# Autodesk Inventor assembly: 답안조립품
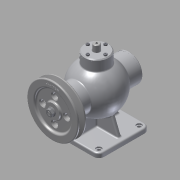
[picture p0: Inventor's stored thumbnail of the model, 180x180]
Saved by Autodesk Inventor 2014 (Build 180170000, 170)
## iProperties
Created: 2015-10
Part Number: 답안조립품
Document SubType Name: Assembly
Designer: youjin08
Author: youjin08
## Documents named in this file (19)
- C:\Users\youjin08\Desktop\451010V1010\답안조립품.iam
- C:\Users\youjin08\Desktop\451010V1010\본체.ipt
- C:\Users\youjin08\Desktop\451010V1010\앞커버.ipt
- C:\Users\youjin08\Desktop\451010V1010\뒤커버.ipt
- C:\Users\youjin08\Desktop\451010V1010\볼트 M4 x 16.ipt
- C:\Users\youjin08\Desktop\451010V1010\상부커버.ipt
- C:\Users\youjin08\Desktop\451010V1010\볼트 M 4 x 12.ipt
- C:\Users\youjin08\Desktop\451010V1010\오일실 15 30 7.ipt
- C:\Users\youjin08\Desktop\451010V1010\베어링- 6202.ipt
- KS B 2023 - 6202 - 15 x 35 x 11 - 7.8.ipt
- C:\Users\youjin08\Desktop\451010V1010\편심축.ipt
- C:\Users\youjin08\Desktop\451010V1010\부시.ipt
- C:\Users\youjin08\Desktop\451010V1010\멈춤링- 35x1.6.ipt
- KS B 1336 - 35x1.6.ipt
- C:\Users\youjin08\Desktop\451010V1010\멈춤링- 15 x 1.ipt
- C:\Users\youjin08\Desktop\451010V1010\키 4 x 4 x 12.ipt
- C:\Users\youjin08\Desktop\451010V1010\V-벨트풀리.ipt
- C:\Users\youjin08\Desktop\451010V1010\너트 M8.ipt
- C:\Users\youjin08\Desktop\451010V1010\슬라이드.ipt
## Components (16 placed, 5 different names)
1. KS B 2023 - 6202 - 15 x 35 x 11 - 7.8:1 — Mate:12, Mate:13, Mate:16, Mate:17, Angle:1
2. KS B 2023 - 6202 - 15 x 35 x 11 - 7.8:2 — Mate:14, Mate:15, Mate:21, Mate:23, Angle:2
3. KS B 1336 - 35x1.6:1 — Mate:23, Mate:24, Angle:4
4. V-벨트풀리:1 — Mate:33, Mate:34, Mate:35
5. ISO 4762 M4 x 16:1 — Insert:1
6. ISO 4762 M4 x 16:2
7. ISO 4762 M4 x 16:3
8. ISO 4762 M4 x 16:4
9. ISO 4762 M4 x 16:5 — Insert:2
10. ISO 4762 M4 x 16:6
11. ISO 4762 M4 x 16:7
12. ISO 4762 M4 x 16:8
13. KS B 1021 - 에 따름 ISO 1207 - 미터 A  M 4 x 12:1 — Insert:3
14. KS B 1021 - 에 따름 ISO 1207 - 미터 A  M 4 x 12:2
15. KS B 1021 - 에 따름 ISO 1207 - 미터 A  M 4 x 12:3
16. KS B 1021 - 에 따름 ISO 1207 - 미터 A  M 4 x 12:4
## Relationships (18: Mate 12, Insert 3, Angle 3)
- Insert:1: ISO 4762 M4 x 16:1
- Insert:2: ISO 4762 M4 x 16:5
- Insert:3: KS B 1021 - 에 따름 ISO 1207 - 미터 A  M 4 x 12:1
- Mate:12: KS B 2023 - 6202 - 15 x 35 x 11 - 7.8:1
- Mate:13: KS B 2023 - 6202 - 15 x 35 x 11 - 7.8:1
- Mate:14: KS B 2023 - 6202 - 15 x 35 x 11 - 7.8:2
- Mate:15: KS B 2023 - 6202 - 15 x 35 x 11 - 7.8:2
- Mate:16: KS B 2023 - 6202 - 15 x 35 x 11 - 7.8:1
- Mate:17: KS B 2023 - 6202 - 15 x 35 x 11 - 7.8:1
- Mate:21: KS B 2023 - 6202 - 15 x 35 x 11 - 7.8:2
- Mate:23: KS B 2023 - 6202 - 15 x 35 x 11 - 7.8:2 ↔ KS B 1336 - 35x1.6:1
- Mate:24: KS B 1336 - 35x1.6:1
- Angle:1: KS B 2023 - 6202 - 15 x 35 x 11 - 7.8:1
- Angle:2: KS B 2023 - 6202 - 15 x 35 x 11 - 7.8:2
- Angle:4: KS B 1336 - 35x1.6:1
- Mate:33: V-벨트풀리:1
- Mate:34: V-벨트풀리:1
- Mate:35: V-벨트풀리:1
